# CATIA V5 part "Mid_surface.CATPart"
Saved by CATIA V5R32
Part number: Part1
Bounding box of the stored display mesh (mm): x -50 to 50, y -40.257 to 69.743, z 0 to 105
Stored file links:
  D:\PROJECTS\Project 2022\CATIA V5 6R 2022\Resources\Part Files\c17_catia_v6_6r2022_prt\Mid_surface.CATPart
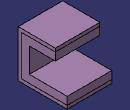
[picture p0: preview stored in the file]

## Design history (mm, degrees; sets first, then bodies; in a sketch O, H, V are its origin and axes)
Body1 (main body)
  Sketch1 on yz-plane, origin (0, 0, 0), H (0, 1, 0), V (0, 0, 1)
    point P1 (-40.2568, 105)
    line L1 (-15.2568, 80) -> (-15.2568, 25)
    line L2 (-40.2568, 0) -> (-40.2568, 105)
    point P3 (-40.2568, 0)
    point P4 (-15.2568, 25)
    line L3 (-15.2568, 25) -> (69.7432, 25)
    line L4 (69.7432, 25) -> (69.7432, 0)
    line L5 (69.7432, 0) -> (-40.2568, 0)
    point P5 (69.7432, 25)
    point P6 (69.7432, 0)
    point P7 (-40.2568, 0)
    reference intersected line E1 through (0, 0) direction (-1, 0) from xy-plane
    reference intersected line E2 through (0, 0) direction (0, 1) from zx-plane
    reference intersected line E4 through (0, 0) direction (0, 1) from zx-plane
    line L6 (-15.2568, 80) -> (43.024, 80)
    line L7 (43.024, 80) -> (43.024, 105)
    line L8 (43.024, 105) -> (-40.2568, 105)
    point P10 (-40.2568, 105)
    distance P4 P5 = 85
    distance L6 L8 = 25
    distance L8 H = 105
    vertical: L1 V, L2 V, L4 V, E2 V, E4 V, L7 V
    horizontal: L3 H, L5 H, E1 H, L6 H, L8 H
    coincidence: P6 H, E1 P3, P1 P10, P3 P7
  Set1
    Extrude1: Element1 Sketch1, Lim1 50, Lim2 50
    MidSurface1: InputSolid Extrude1, FacePairs ({midsurfacefacepair Face1 face of Extrude1 from Sketch1.L3, Face2 face of Extrude1 from Sketch1.L5}; {midsurfacefacepair Face1 face of Extrude1 from Sketch1.L1, Face2 face of Extrude1 from Sketch1.L2}; {midsurfacefacepair Face1 face of Extrude1 from Sketch1.L6, Face2 face of Extrude1 from Sketch1.L8}), OffsetRatio 0.3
